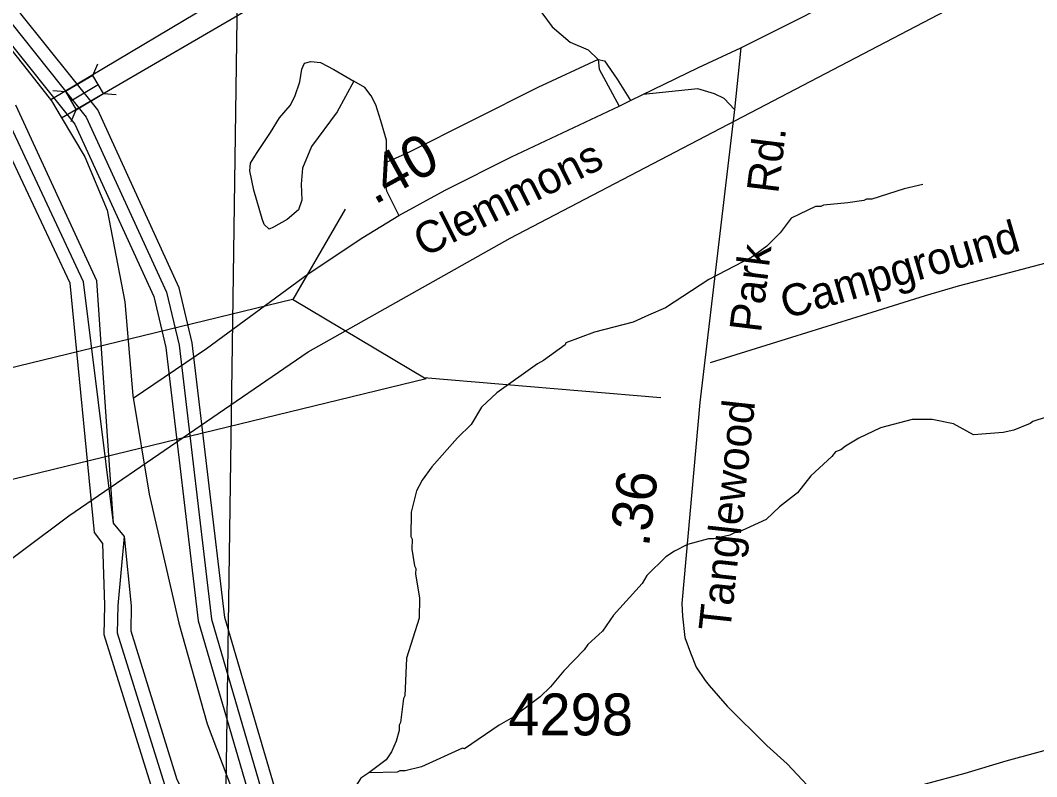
# Model space of a CAD drawing. Extents: x 1547597 to 1699558, y 810033 to 920809.
# Drawn here: x 1580417 to 1583449, y 825864 to 828120 of the extents above; entities that cross this region are included whole.
import ezdxf

# ---------------------------------------------------------------- set-up
doc = ezdxf.new("R2010")
doc.units = 0
for name, color, linetype in [('Exist Boundary Political City Limit New', 7, 'Continuous'), ('Exist Boundary Political CountyLine', 7, 'Continuous'), ('Exist Hydrographic Bay Label', 7, 'Continuous'), ('Exist Hydrographic Buffer Line', 7, 'Continuous'), ('Exist Hydrographic Misc Water Feature', 7, 'Continuous'), ('Exist Road Non-System Type 51', 7, 'Continuous'), ('Exist Road Non-System Type 51 Label', 7, 'Continuous'), ('Exist Road Primary Interstate Divided Center Attributed', 7, 'Continuous'), ('Exist Road Primary Interstate Structure Standard Bridge CELL', 7, 'Continuous'), ('Exist Road Primary US Attributed', 7, 'Continuous'), ('Exist Road Primary US Label', 7, 'Continuous'), ('Exist Road Primary US Mileage Hundredths English Label', 7, 'Continuous'), ('Exist Road Primary US Structure Standard Bridge CELL', 7, 'Continuous'), ('Exist Road Secondary Mileage Hundredths English Label', 7, 'Continuous'), ('Exist Road Secondary Type 51 Attributed', 7, 'Continuous'), ('Exist Road Secondary Type 51 Label', 7, 'Continuous'), ('Exist Road Secondary Type 51 Number Label', 7, 'Continuous'), ('Map Preparation Boundary City Limit Buffer Line', 7, 'Continuous'), ('Map Preparation Longitude Latitude Lines', 7, 'Continuous')]:
    doc.layers.add(name, color=color, linetype=linetype)

msp = doc.modelspace()

# ---------------------------------------------------------------- linework, layer by layer
at = {"layer": 'Exist Boundary Political City Limit New'}
msp.add_lwpolyline([(1580015.1, 826233.8), (1580561.4, 826641.6), (1581275.8, 827130.9), (1581878.1, 827470.7), (1583334.9, 828231.8), (1583783.1, 828462.9), (1584777.6, 828666.8), (1585436, 828829.9), (1585940.2, 828979.4), (1586206.4, 828925), (1586150.3, 826233.8), (1584385.4, 825907.6), (1585225.9, 823361.7)], dxfattribs=at)
at = {"layer": 'Exist Boundary Political CountyLine'}
msp.add_lwpolyline([(1580254, 828203.3), (1580426.1, 827986.9), (1580509.6, 827880.1), (1580538.9, 827831.1), (1580609.4, 827713), (1580675.6, 827554), (1580728.5, 827280.2), (1580752.2, 827000.4), (1580801.4, 826706), (1580889.7, 826321.7), (1580973.5, 826021.4), (1581119.2, 825637.1)], dxfattribs=at)
at = {"layer": 'Exist Hydrographic Bay Label'}
for points in [[(1580668.5, 826375.2), (1580662.5, 826559.1), (1580637.5, 826592.5), (1580565.6, 827335.8), (1580330.6, 827832.9), (1580035.5, 828186.9), (1579780.5, 828408.7), (1579524.5, 828578), (1579146.5, 828923.9), (1578832.6, 829169.8), (1577169.5, 830027.5), (1576789.5, 830274.8), (1576740.5, 830344.7), (1576649.5, 830385.9), (1576262.5, 830718.8), (1576204.5, 830743)], [(1581965.5, 823873.7), (1581867.5, 824016.9), (1581706.6, 824378), (1581658.6, 824520.1), (1581561.5, 824722.3), (1581505.5, 824930.2), (1581481.5, 824947.2), (1581281.5, 825574.9), (1581208.5, 825717.5), (1581026.5, 826338.4), (1580929.5, 827157.8), (1580890.6, 827322.6), (1580647.6, 827852.8), (1580418.5, 828139.8), (1579786.6, 828825.5), (1579044.5, 829428.1), (1578498.5, 829718.2)], [(1581462.7, 821936.1), (1581776.6, 822308.5), (1581820.6, 822475), (1581820.6, 823042.9), (1581584.6, 824012.8), (1581559.5, 824029.7), (1581552.6, 824111.9), (1581535.6, 824128.6), (1581457.5, 824438.8), (1581375.5, 824565.2), (1581376.5, 824614.4), (1581319.5, 824723.9), (1581166.6, 825111.1), (1581085.6, 825237.5), (1581077.6, 825296.8), (1580810.5, 825824.1), (1580666.5, 826286.6), (1580668.5, 826375.2)]]:
    msp.add_lwpolyline(points, dxfattribs=at)
at = {"layer": 'Exist Hydrographic Buffer Line'}
for points in [[(1580388.2, 828113.8), (1580613.2, 827831.7), (1580852.5, 827309.5), (1580890, 827150.8), (1580986.8, 826333.7), (1581170.1, 825706.3)], [(1580357.7, 828087.7), (1580578.9, 827810.5), (1580814.5, 827296.5), (1580850.6, 827143.8), (1580947.1, 826329), (1581131.7, 825695), (1581207.8, 825543.3), (1581429, 824906.6), (1581484.3, 824701.5), (1581584.4, 824489.9)], [(1581584.4, 824489.9), (1581456, 824588.1), (1581392.4, 824757.2), (1581241, 825140.5), (1581162.5, 825265.7), (1581148.9, 825332.9), (1580884.9, 825854.3), (1580746.8, 826297.9), (1580748.5, 826373.4), (1580727.2, 826580.5), (1580695, 826620), (1580645.2, 827343.5), (1580402.8, 827867.1)], [(1580352.2, 821096.6), (1580854, 821477.1), (1581256.3, 821720.5), (1581487.6, 821904.8), (1581807.1, 822282.7), (1581859.2, 822464.8), (1581860.6, 823042.9), (1581623.4, 824022.2), (1581590.8, 824123.6), (1581496, 824450), (1581415.8, 824576.7), (1581399, 824622.6), (1581355.9, 824740.5), (1581203.8, 825125.8), (1581124, 825251.6), (1581098.3, 825306.5), (1580847.7, 825839.2), (1580706.6, 826292.2), (1580708.5, 826374.3), (1580727.2, 826580.5), (1580695, 826620), (1580605.3, 827339.6), (1580366.8, 827850)]]:
    msp.add_lwpolyline(points, dxfattribs=at)
at = {"layer": 'Exist Hydrographic Misc Water Feature'}
for points in [[(1583109.5, 827630.9), (1583053.3, 827617.6), (1582957.1, 827586.8), (1582941.1, 827587), (1582933, 827583.1), (1582884.9, 827575.7), (1582812.8, 827568.6), (1582804.8, 827564.7), (1582788.8, 827564.9), (1582716.4, 827529.9), (1582683.9, 827486.3), (1582643.4, 827446.8), (1582599.1, 827413.4), (1582470.3, 827347), (1582341.3, 827262.7), (1582290.7, 827240.2), (1582244.7, 827219.6), (1582129.6, 827189.5), (1582044.2, 827158.5), (1582042.1, 827152.5), (1581977.5, 827105.3), (1581959.4, 827095.6), (1581838.4, 827009.1), (1581792, 826965.7), (1581761.3, 826914.2), (1581720.8, 826874.7), (1581643.8, 826787.7), (1581615.4, 826748.1), (1581599, 826716.3), (1581582.3, 826652.5), (1581581.4, 826580.5), (1581585.3, 826572.5), (1581585, 826542.5), (1581592.4, 826492.5), (1581596.2, 826484.4), (1581596, 826468.4), (1581607.2, 826396.3), (1581606.5, 826336.3), (1581569.1, 826216.9), (1581563.7, 826105), (1581559.6, 826097), (1581550.8, 826025.2), (1581546.7, 826017.3), (1581546.5, 826001.3), (1581538.2, 825969.4), (1581523.8, 825937.5), (1581507.6, 825913.8), (1581456.7, 825874.5)], [(1583477.2, 826936.6), (1583437.1, 826923.1), (1583429, 826917.2), (1583380.8, 826897.8), (1583348.7, 826890.2), (1583260.7, 826883.3), (1583201, 826916), (1583137.2, 826928.8), (1583077.2, 826929.6), (1582982.9, 826904.8), (1582918.6, 826873.6), (1582878.3, 826850.1), (1582864.2, 826838.3), (1582848.1, 826832.5), (1582837.9, 826818.6), (1582775.3, 826761.4), (1582734.7, 826710), (1582681.6, 826668.2), (1582641.8, 826631.2), (1582557.3, 826592.3), (1582549.3, 826592.4), (1582533.2, 826584.6), (1582485.1, 826573.2), (1582469.2, 826573.4), (1582406.9, 826556.2), (1582368.7, 826536.7), (1582342.5, 826519), (1582285.8, 826463.8), (1582271.6, 826439.9), (1582186.5, 826345), (1582153.9, 826297.5), (1582109.5, 826258), (1582099.2, 826242.2), (1582038.5, 826179), (1581997.9, 826131.5), (1581967.6, 826101.9), (1581886.9, 826040.9), (1581844.7, 826017.5), (1581741.8, 825946.8), (1581735.9, 825948.6), (1581613.3, 825892.5), (1581565.1, 825881), (1581549.1, 825881.3), (1581541.1, 825877.4), (1581456.7, 825874.5)], [(1581456.7, 825874.5), (1581432.9, 825858.7), (1581414.6, 825831), (1581392.3, 825811.3), (1581376.2, 825805.5), (1581344.3, 825807.9), (1581336.3, 825812), (1581288.4, 825808.6), (1581272.3, 825804.8), (1581224.6, 825779.9)]]:
    msp.add_lwpolyline(points, dxfattribs=at)
at = {"layer": 'Exist Road Non-System Type 51'}
for points in [[(1581938.4, 828292.1), (1581953.7, 828189), (1581972.8, 828143.1), (1582003.4, 828101.1), (1582056.8, 828055.2), (1582110.3, 828032.3), (1582140, 828003.7)], [(1582140, 828003.7), (1581960.4, 827919.6), (1581572.5, 827724.7), (1581507.6, 827696.1)], [(1582140, 828003.7), (1582159.1, 827999.8), (1582197.3, 827944.4), (1582237.4, 827881.4)], [(1582140, 828003.7), (1582143.8, 827975), (1582203, 827864.2)], [(1581507.6, 827696.1), (1581509.5, 827762.9), (1581492.3, 827820.2), (1581477, 827868), (1581463.6, 827894.8), (1581444.5, 827919.6), (1581412, 827938.7)], [(1582546.9, 827854.6), (1582516.3, 827887.1), (1582487.7, 827900.5), (1582438, 827915.8), (1582274.6, 827899.4)], [(1581507.6, 827696.1), (1581501.8, 827644.5), (1581509.5, 827612), (1581522.9, 827583.3), (1581545.8, 827537.5)], [(1584285.9, 826863.5), (1584272.9, 827485.9), (1584273.1, 827507.9), (1584267.4, 827530.1), (1584253.8, 827552.4), (1584233.9, 827568.6), (1584214.1, 827575), (1584188.1, 827577.3), (1584158, 827575.7), (1584117.9, 827568.3), (1584041.6, 827545.4), (1583366.8, 827367), (1583214.1, 827327.3), (1583115.7, 827298.6), (1582940.6, 827243.2), (1582717.7, 827174.4), (1582474.4, 827097.9)], [(1582524.9, 826074), (1582644, 825956.6), (1582704.5, 825902.1)], [(1582811.5, 825788.4), (1582843.6, 825779.9), (1582863.6, 825779.5), (1582887.6, 825783.3), (1582935.7, 825794.6), (1583000, 825807.5), (1583116.6, 825842), (1583235.1, 825874.2), (1583357.7, 825910.6), (1583691.1, 826001.7), (1583731.3, 826009.1), (1583769.4, 826024.5), (1583805.8, 826040), (1583860, 826059.3)], [(1582704.5, 825902.1), (1582780.1, 825820.8), (1582793.8, 825804.5), (1582811.5, 825788.4)]]:
    msp.add_lwpolyline(points, dxfattribs=at)
msp.add_lwpolyline([(1581412, 827938.7), (1581361.4, 827847), (1581285, 827743.8), (1581258.2, 827678.9), (1581254.4, 827631.1), (1581256.3, 827583.3), (1581246.8, 827554.7), (1581212.4, 827526), (1581172.3, 827503.1), (1581158.9, 827497.4), (1581143.6, 827510.7), (1581137.9, 827527.9), (1581113, 827613.9), (1581101.6, 827671.2), (1581103.5, 827694.2), (1581120.7, 827722.8), (1581162.7, 827785.9), (1581189.5, 827829.8), (1581221.9, 827866.1), (1581235.3, 827892.8), (1581250.6, 827936.8), (1581256.3, 827975), (1581264, 827992.2), (1581283.1, 827997.9), (1581311.7, 827994.1), (1581351.9, 827973.1)], close=True, dxfattribs=at)
at = {"layer": 'Exist Road Primary Interstate Divided Center Attributed'}
for points in [[(1584528.8, 830234.7), (1584290.7, 830093.3), (1584094.5, 829978.6), (1583401.4, 829573.8), (1581098.9, 828235.9), (1580507.2, 827883.1)], [(1580539.7, 827829.7), (1581661.5, 828482.9), (1583505.8, 829557.3), (1584270.9, 830014.6), (1584525.9, 830165.7)]]:
    msp.add_lwpolyline(points, dxfattribs=at)
at = {"layer": 'Exist Road Primary Interstate Structure Standard Bridge CELL'}
for p, q in [((1580632.9, 827955.9), (1580648.2, 827990.3)), ((1580567.2, 827880.5), (1580648.9, 827928.8)), ((1580513.5, 827910.9), (1580551.1, 827907.7)), ((1580664.7, 827902.1), (1580702.3, 827898.8)), ((1580568, 827818.8), (1580583.3, 827853.2))]:
    msp.add_line(p, q, dxfattribs=at)
msp.add_lwpolyline([(1580583.3, 827853.2), (1580665, 827901.6), (1580632.8, 827956), (1580551.1, 827907.7)], close=True, dxfattribs=at)
at = {"layer": 'Exist Road Primary US Attributed'}
for points in [[(1582565.9, 828038.6), (1583357.5, 828436.3), (1583627.8, 828575), (1583742.4, 828614.1), (1583798.4, 828629.4), (1583862.1, 828643), (1583929.9, 828653), (1584275.8, 828709), (1584473.8, 828749.5)], [(1580753.4, 826992.9), (1580972.1, 827141.1), (1581275, 827363.6), (1581438.3, 827472.5), (1581545.8, 827537.5), (1581684.2, 827613.5), (1581882.2, 827712.6), (1582203, 827864.2), (1582237.4, 827881.4), (1582439.6, 827979.5), (1582565.9, 828038.6)]]:
    msp.add_lwpolyline(points, dxfattribs=at)
at = {"layer": 'Exist Road Primary US Structure Standard Bridge CELL'}
for p, q in [((1581230.6, 827287.1), (1581387.1, 827556.6)), ((1581620.1, 827054.4), (1582327.4, 826994.8))]:
    msp.add_line(p, q, dxfattribs=at)
msp.add_lwpolyline([(1579891, 826963.3), (1581228.8, 827288.3), (1581627.3, 827050.2), (1580289.5, 826725.2)], close=True, dxfattribs=at)
at = {"layer": 'Exist Road Secondary Type 51 Attributed'}
msp.add_lwpolyline([(1582565.9, 828038.6), (1582546.9, 827854.6), (1582443.9, 826979.7), (1582389.6, 826380.7), (1582391.8, 826342.8), (1582398.8, 826278.5), (1582416, 826232.6), (1582433.2, 826190.6), (1582459.4, 826150.2), (1582472, 826135.4), (1582524.9, 826074)], dxfattribs=at)
at = {"layer": 'Map Preparation Boundary City Limit Buffer Line'}
msp.add_lwpolyline([(1580015.1, 826233.8), (1580561.4, 826641.6), (1581275.8, 827130.9), (1581878.1, 827470.7), (1583334.9, 828231.8), (1583783.1, 828462.9), (1584777.6, 828666.8), (1585436, 828829.9), (1585940.2, 828979.4), (1586206.4, 828925), (1586150.3, 826233.8), (1584385.4, 825907.6), (1585225.9, 823361.7)], dxfattribs=at)
at = {"layer": 'Map Preparation Longitude Latitude Lines'}
msp.add_lwpolyline([(1580937.1, 819298.5), (1580964.9, 821247.5), (1581064, 828194.9)], dxfattribs=at)

# ---------------------------------------------------------------- texts
at = {"layer": 'Exist Road Non-System Type 51 Label'}
msp.add_text('Campground', height=95, rotation=16.2608, dxfattribs=at).set_placement((1582700.4, 827228.8))
at = {"layer": 'Exist Road Primary US Label'}
msp.add_text('Clemmons', height=95, rotation=26.5735, dxfattribs=at).set_placement((1581620.5, 827412.2))
at = {"layer": 'Exist Road Primary US Mileage Hundredths English Label'}
msp.add_text('.40', height=125, rotation=28.7744, dxfattribs=at).set_placement((1581472.5, 827568.6))
at = {"layer": 'Exist Road Secondary Mileage Hundredths English Label'}
msp.add_text('.36', height=120, rotation=83.0021, dxfattribs=at).set_placement((1582292, 826546.9))
at = {"layer": 'Exist Road Secondary Type 51 Label'}
for s, rotation, p in [('Rd.', 83.0021, (1582677.6, 827601.3)), ('Park', 83.0021, (1582626, 827186.3)), ('Tanglewood', 83.7942, (1582534.1, 826294.3))]:
    msp.add_text(s, height=95, rotation=rotation, dxfattribs=at).set_placement(p)
at = {"layer": 'Exist Road Secondary Type 51 Number Label'}
msp.add_text('4298', height=125, dxfattribs=at).set_placement((1581872.4, 825986.8))

doc.saveas('drawing.dxf')
